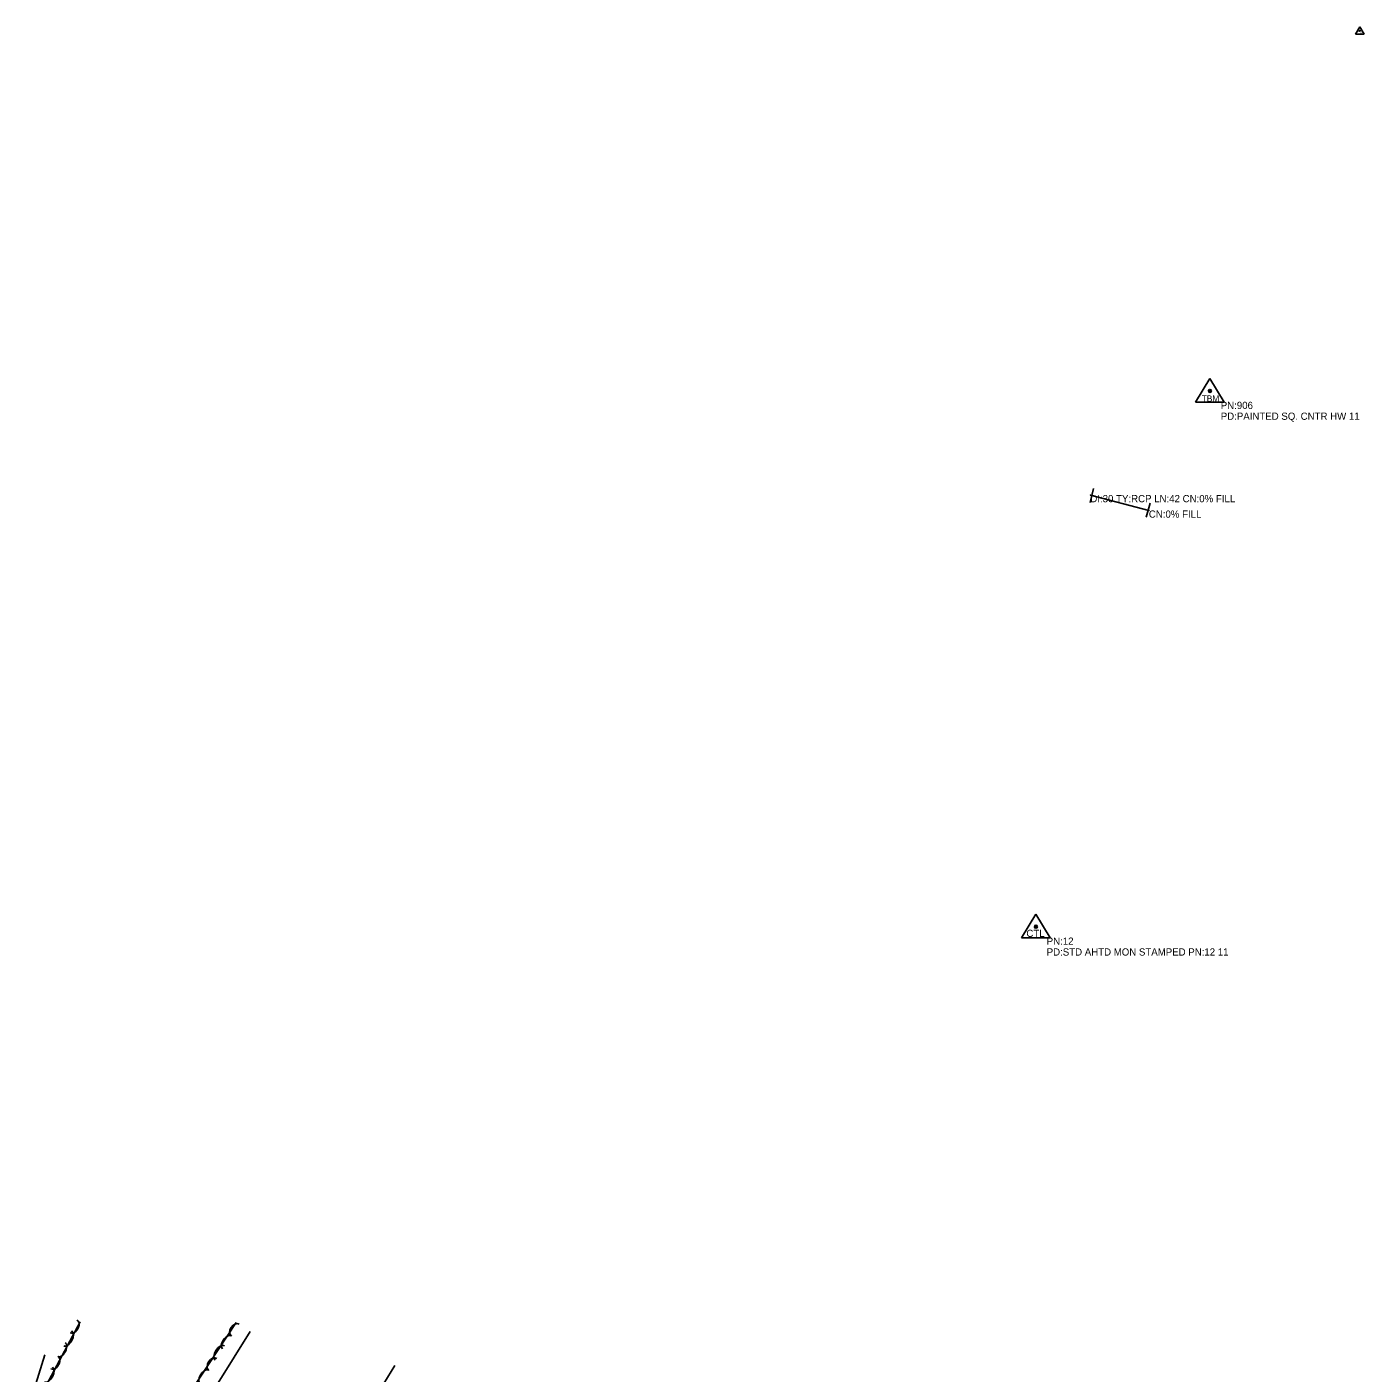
# Model space of a CAD drawing. Extents: x 1451369 to 1458940, y 1868647 to 1875095.
# Drawn here: x 1454661 to 1455587, y 1872730 to 1873663 of the extents above; entities that cross this region are included whole.
import ezdxf

# ---------------------------------------------------------------- set-up
doc = ezdxf.new("R2010")
doc.units = 0
for name, color, linetype in [('E_ROW Point Number', 7, 'Continuous'), ('E_Station Offset', 7, 'Continuous'), ('E_Tract Number', 7, 'Continuous'), ('E_Tract Residual', 7, 'Continuous'), ('R_No Plot', 7, 'Continuous'), ('S_CROSS_DRAIN', 7, 'Continuous'), ('S_CROSS_DRAIN_ANNOT', 7, 'Continuous'), ('S_HEADWALL', 7, 'Continuous'), ('S_PRIMARY_CTL_ANNOT', 7, 'Continuous')]:
    doc.layers.add(name, color=color, linetype=linetype)

msp = doc.modelspace()

# ---------------------------------------------------------------- linework, layer by layer
at = {"layer": 'E_ROW Point Number'}
for points in [[(1454697.82, 1872765.68), (1454672.67, 1872718.55)], [(1454768.21, 1872707.66), (1454805.96, 1872765.14)]]:
    msp.add_lwpolyline(points, dxfattribs=at)
for centre, major_axis, ratio, start_param, end_param in [((1454693.39, 1872762.43), (2.34, 4.36), 0.684198, 3.146397, 6.28799), ((1454805.35, 1872759.87), (-2.72, -4.14), 0.685257, 3.141516, 6.283108), ((1454689.26, 1872754.14), (2.77, 5.17), 0.54919, 3.14453, 6.286122), ((1454799.48, 1872751.41), (-2.94, -4.47), 0.540657, 3.141547, 6.28314), ((1454685.1, 1872746.33), (2.52, 4.71), 0.539825, 3.144438, 6.286031), ((1454794.61, 1872744), (-3.22, -4.9), 0.550037, 3.141546, 6.283138), ((1454680.02, 1872737.37), (2.34, 4.36), 0.684198, 3.146397, 6.28799), ((1454789.75, 1872736.11), (-2.72, -4.14), 0.685257, 3.141516, 6.283108), ((1454675.9, 1872729.09), (2.77, 5.17), 0.54919, 3.14453, 6.286122), ((1454783.87, 1872727.65), (-2.94, -4.47), 0.540657, 3.141547, 6.28314)]:
    msp.add_ellipse(centre, major_axis=major_axis, ratio=ratio, start_param=start_param, end_param=end_param, dxfattribs=at)
at = {"layer": 'E_Station Offset'}
for p, q in [((1455584.23, 1873662.76), (1455581.22, 1873657.81)), ((1455584.23, 1873662.76), (1455587.18, 1873657.81)), ((1455581.22, 1873657.81), (1455587.18, 1873657.81))]:
    msp.add_line(p, q, dxfattribs=at)
for radius in [0.311, 0.183, 0.103]:
    msp.add_circle((1455584.23, 1873660.15), radius, dxfattribs=at)
at = {"layer": 'E_Tract Number'}
for points in [[(1455397.59, 1873338.44), (1455397.59, 1873338.49), (1455397.59, 1873338.44), (1455397.54, 1873338.44), (1455397.59, 1873338.44), (1455397.59, 1873338.39), (1455397.59, 1873338.44), (1455397.64, 1873338.44)], [(1455438.11, 1873327.76), (1455438.11, 1873327.81), (1455438.11, 1873327.76), (1455438.06, 1873327.76), (1455438.11, 1873327.76), (1455438.11, 1873327.71), (1455438.11, 1873327.76), (1455438.16, 1873327.76)]]:
    msp.add_lwpolyline(points, dxfattribs=at)
at = {"layer": 'E_Tract Residual'}
for points in [[(1454793.46, 1872723.46), (1454815.66, 1872758.88)], [(1454673.42, 1872742.75), (1454661.05, 1872702.55)], [(1454915.78, 1872735.4), (1454882.85, 1872681.3), (1454846.79, 1872587.87)]]:
    msp.add_lwpolyline(points, dxfattribs=at)
at = {"layer": 'R_No Plot'}
for p, q in [((1455480.41, 1873419.26), (1455470.38, 1873402.75)), ((1455480.41, 1873419.26), (1455490.24, 1873402.75)), ((1455470.38, 1873402.75), (1455490.24, 1873402.75)), ((1455359.86, 1873048.07), (1455349.83, 1873031.55)), ((1455359.86, 1873048.07), (1455369.69, 1873031.55)), ((1455349.83, 1873031.55), (1455369.69, 1873031.55))]:
    msp.add_line(p, q, dxfattribs=at)
for centre, radius in [((1455480.41, 1873410.56), 1.04), ((1455480.41, 1873410.56), 0.609), ((1455480.41, 1873410.56), 0.344), ((1455359.86, 1873039.37), 1.04), ((1455359.86, 1873039.37), 0.609), ((1455359.86, 1873039.37), 0.344)]:
    msp.add_circle(centre, radius, dxfattribs=at)
at = {"layer": 'S_CROSS_DRAIN'}
msp.add_line((1455397.59, 1873338.44), (1455438.11, 1873327.76), dxfattribs=at)
at = {"layer": 'S_HEADWALL'}
for points in [[(1455399.77, 1873342.97), (1455397.37, 1873333.35)], [(1455436.35, 1873323.12), (1455438.95, 1873332.81)]]:
    msp.add_lwpolyline(points, dxfattribs=at)

# ---------------------------------------------------------------- texts
at = {"layer": 'E_Station Offset'}
msp.add_text('TV', height=1.5, rotation=360, dxfattribs=at).set_placement((1455583.03, 1873658.14))
at = {"layer": 'R_No Plot'}
for s, height, p in [('TBM', 4.287, (1455474.76, 1873403.17)), ('CTL', 5, (1455353.28, 1873032.29))]:
    msp.add_text(s, height=height, rotation=360, dxfattribs=at).set_placement(p)
at = {"layer": 'S_CROSS_DRAIN_ANNOT'}
for s, p in [('DI:30 TY:RCP LN:42 CN:0% FILL', (1455397.59, 1873333.44)), ('CN:0% FILL', (1455438.11, 1873322.76))]:
    msp.add_text(s, height=5, dxfattribs=at).set_placement(p)
at = {"layer": 'S_PRIMARY_CTL_ANNOT'}
for s, p in [('PN:906', (1455487.91, 1873398.06)), ('PD:PAINTED SQ. CNTR HW 11', (1455487.91, 1873390.56)), ('PN:12', (1455367.36, 1873026.87)), ('PD:STD AHTD MON STAMPED PN:12 11', (1455367.36, 1873019.37))]:
    msp.add_text(s, height=5, dxfattribs=at).set_placement(p)

doc.saveas('drawing.dxf')
